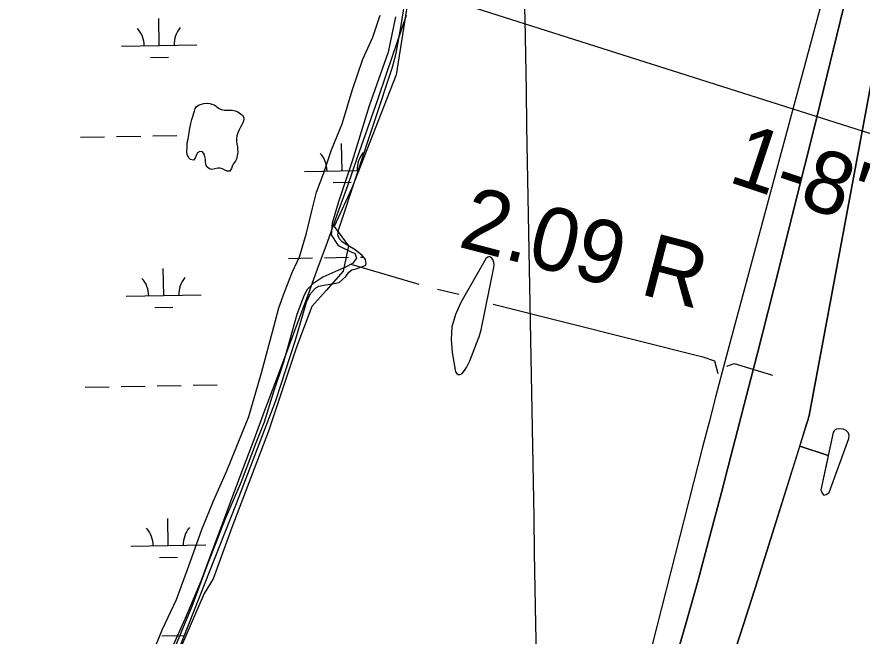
# Model space of a CAD drawing. Extents: x 3925854 to 3964121, y 224593 to 250589.
# Drawn here: x 3940034 to 3941160, y 231956 to 232780 of the extents above; entities that cross this region are included whole.
import ezdxf

# ---------------------------------------------------------------- set-up
doc = ezdxf.new("R2010")
doc.units = 0
for name, color, linetype in [('V-GRID-MAJR', 7, 'Continuous'), ('V-LEVE-TOET', 7, 'Continuous'), ('V-RIVR-EDGE', 7, 'Continuous'), ('V-RIVR-JETY', 7, 'Continuous'), ('V-RIVR-RANG-IDEN', 7, 'Continuous'), ('V-RRAP-FSHR', 7, 'Continuous'), ('V-TOPO-DPTH', 7, 'Continuous'), ('V-TOPO-MINR', 7, 'Continuous'), ('V-TOPO-SHOR', 7, 'Continuous'), ('V-UTIL-IDEN', 7, 'Continuous'), ('V-UTIL-LINE', 7, 'Continuous'), ('V-WETL-SWMP', 7, 'Continuous')]:
    doc.layers.add(name, color=color, linetype=linetype)

msp = doc.modelspace()

# ---------------------------------------------------------------- linework, layer by layer
at = {"layer": 'V-GRID-MAJR'}
msp.add_spline([(3940756.893, 230221.23), (3940647.643, 236278.076), (3940538.337, 242338.005), (3940429.031, 248397.924), (3940428.975, 248401.018)], degree=3, dxfattribs=at)
at = {"layer": 'V-LEVE-TOET'}
for p, q in [((3940478.73, 232450.733), (3940569.213, 232424.402)), ((3940594.108, 232417.387), (3940622.633, 232411.016))]:
    msp.add_line(p, q, dxfattribs=at)
for points in [[(3940668.18, 232397.55), (3940947.413, 232327.718), (3940963.209, 232322.428), (3940967.618, 232305.519)], [(3940979.628, 232315.329), (3940989.284, 232318.454), (3941040.3, 232303.228)]]:
    msp.add_lwpolyline(points, dxfattribs=at)
at = {"layer": 'V-RIVR-EDGE'}
msp.add_lwpolyline([(3940558.753, 232826.474), (3940539.303, 232702.605), (3940479.927, 232552.119), (3940456.382, 232500.933), (3940475.833, 232475.34), (3940468.667, 232441.558), (3940446.145, 232415.965), (3940426.694, 232394.467), (3940406.22, 232340.21), (3940369.366, 232228.626), (3940320.228, 232100.662), (3940295.659, 232032.073), (3940283.375, 232012.622), (3940247.545, 231929.702)], dxfattribs=at)
at = {"layer": 'V-RIVR-JETY'}
for points in [[(3940410.212, 232460.649), (3940419.618, 232492.182), (3940427.876, 232525.294), (3940433.24, 232546.718), (3940442.959, 232572.386), (3940453.138, 232603.126), (3940467.271, 232637.332), (3940481.169, 232683.267), (3940494.604, 232723.733), (3940507.887, 232752.87), (3940517.654, 232782.052)], [(3940538.339, 232779.826), (3940528.339, 232733.058), (3940503.156, 232661.478), (3940480.686, 232587.91), (3940462.381, 232533.826), (3940453.798, 232505.408), (3940452.808, 232489.788), (3940462, 232475.598), (3940481.028, 232466.355), (3940484.145, 232465.532), (3940486.402, 232458.857), (3940481.226, 232451.892), (3940470.603, 232446.561), (3940461.258, 232442.397)], [(3940313.796, 232175.699), (3940342.732, 232248.044), (3940360.007, 232306.044), (3940376.336, 232367.668), (3940382.742, 232392.86), (3940390.406, 232413.525), (3940400.738, 232439.665), (3940410.212, 232460.649)], [(3940461.258, 232442.397), (3940441.366, 232433.417), (3940428.134, 232424.805), (3940420.04, 232416.851), (3940415.897, 232407.424), (3940406.749, 232384.019), (3940389.226, 232320.568), (3940375.412, 232279.559), (3940363.393, 232240.686), (3940352.766, 232213.937), (3940332.712, 232161.359), (3940310.528, 232109.667), (3940286.627, 232048.27), (3940267.182, 231995.395), (3940236.439, 231921.82)], [(3940207.444, 231915.168), (3940227.829, 231965.025), (3940246.501, 232004.572), (3940263.004, 232049.243), (3940280.373, 232097.856), (3940296.032, 232136.162), (3940313.796, 232175.699)]]:
    msp.add_lwpolyline(points, dxfattribs=at)
at = {"layer": 'V-RRAP-FSHR'}
msp.add_lwpolyline([(3940552.433, 232781.786), (3940539.558, 232743.914), (3940526.682, 232706.43), (3940513.806, 232668.173), (3940500.633, 232630.404), (3940487.385, 232592.661), (3940474.136, 232554.919), (3940460.787, 232517.213), (3940447.49, 232479.646), (3940433.309, 232442.791), (3940419.571, 232404.513), (3940405.645, 232367.16), (3940391.602, 232329.563), (3940377.559, 232292.109), (3940363.516, 232254.655), (3940349.472, 232217.201), (3940335.427, 232179.748), (3940321.384, 232142.294), (3940307.343, 232104.84), (3940293.298, 232067.386), (3940279.255, 232029.932), (3940258.246, 231979.478), (3940241.936, 231942.954)], dxfattribs=at)
at = {"layer": 'V-TOPO-DPTH'}
for points in [[(3941197.73, 232828.069), (3941182.541, 232749.068), (3941089.043, 232249.474), (3941088.463, 232246.844), (3941087.715, 232244.258), (3941086.484, 232240.404), (3941086.08, 232239.118), (3941042.756, 232100.204), (3941020.439, 232029.543), (3940997.785, 231958.991), (3940974.625, 231888.603), (3940951.128, 231818.325), (3940831.453, 231527.83), (3940778.585, 231417.807), (3940749.942, 231356.296), (3940722.307, 231294.349), (3940696.185, 231231.75), (3940671.071, 231168.715), (3940471.587, 230649.777), (3940468.564, 230644.623), (3940464.787, 230640.393), (3940233.897, 230211.72)], [(3941076.606, 232208.74), (3941086.08, 232239.118), (3941086.484, 232240.404), (3941087.715, 232244.258), (3941088.463, 232246.844), (3941089.043, 232249.474), (3941182.541, 232749.068), (3941197.73, 232828.069)], [(3940589.961, 231081.241), (3940627.394, 231165.87), (3940800.448, 231552.151), (3940801.441, 231554.375), (3940803.409, 231558.832), (3940805.314, 231563.313), (3940806.969, 231567.884), (3940807.696, 231570.207), (3940908.212, 231914.462), (3940924.869, 231972.465), (3940941.18, 232030.563), (3940956.975, 232088.804), (3940972.426, 232147.139), (3940984.998, 232195.477), (3940993.875, 232229.723), (3941002.714, 232263.978), (3941011.497, 232298.248), (3941020.241, 232332.528), (3941049.078, 232445.972), (3941072.045, 232537.023), (3941094.788, 232628.129), (3941117.196, 232719.318), (3941139.38, 232810.562)], [(3941108.765, 232143.607), (3941112.007, 232144.356), (3941115.854, 232147.185), (3941142.154, 232218.659), (3941142.342, 232223.098), (3941141.312, 232226.774), (3941138.455, 232229.307), (3941134.38, 232231.078), (3941127.905, 232231.725), (3941125.618, 232231.406), (3941123.697, 232230.585), (3941122.323, 232229.01), (3941121.315, 232226.933), (3941114.613, 232196.067), (3941076.606, 232208.74)], [(3941108.765, 232143.607), (3941112.007, 232144.356), (3941115.854, 232147.185), (3941142.154, 232218.659), (3941142.342, 232223.098), (3941141.312, 232226.774), (3941138.455, 232229.307), (3941134.38, 232231.078), (3941127.905, 232231.725), (3941125.618, 232231.406), (3941123.697, 232230.585), (3941122.323, 232229.01), (3941121.315, 232226.933), (3941104.703, 232150.43), (3941106.431, 232145.978), (3941108.765, 232143.607)], [(3941075.21, 232204.264), (3941076.606, 232208.74), (3941114.613, 232196.067), (3941113.153, 232189.344), (3941104.703, 232150.43), (3941106.431, 232145.978), (3941108.765, 232143.607)], [(3940376.027, 230214.305), (3940233.897, 230211.72), (3940464.787, 230640.393), (3940468.564, 230644.623), (3940471.587, 230649.777), (3940671.071, 231168.715), (3940696.185, 231231.75), (3940722.307, 231294.349), (3940749.942, 231356.296), (3940778.585, 231417.807), (3940831.453, 231527.83), (3940951.128, 231818.325), (3940974.625, 231888.603), (3940997.785, 231958.991), (3941020.439, 232029.543), (3941042.756, 232100.204), (3941075.21, 232204.264)]]:
    msp.add_lwpolyline(points, dxfattribs=at)
at = {"layer": 'V-TOPO-MINR'}
for points in [[(3941127.416, 232879.626), (3940982.328, 232340.733), (3940973.425, 232307.411), (3940964.606, 232274.067), (3940955.914, 232240.69), (3940947.307, 232207.29), (3940849.808, 231825.96), (3940838.71, 231783.378), (3940827.35, 231740.867), (3940815.597, 231698.463), (3940803.581, 231656.131), (3940779.662, 231573.33), (3940779.395, 231572.457), (3940778.793, 231570.733), (3940777.755, 231568.196), (3940777.396, 231567.355), (3940777.032, 231566.517), (3940475.423, 230877.328)], [(3941197.73, 232828.069), (3941182.541, 232749.068), (3941089.043, 232249.474), (3941088.463, 232246.844), (3941087.715, 232244.258), (3941086.484, 232240.404), (3941086.08, 232239.118), (3941042.756, 232100.204), (3941020.439, 232029.543), (3940997.785, 231958.991), (3940974.625, 231888.603), (3940951.128, 231818.325), (3940831.453, 231527.83), (3940778.585, 231417.807), (3940749.942, 231356.296), (3940722.307, 231294.349), (3940696.185, 231231.75), (3940671.071, 231168.715), (3940471.587, 230649.777), (3940468.564, 230644.623), (3940464.787, 230640.393), (3940233.897, 230211.72)], [(3941139.38, 232810.562), (3941117.196, 232719.318), (3941094.788, 232628.129), (3941072.045, 232537.023), (3941049.078, 232445.972), (3941020.241, 232332.528), (3941011.497, 232298.248), (3941002.714, 232263.978), (3940993.875, 232229.723), (3940984.998, 232195.477), (3940972.426, 232147.139), (3940956.975, 232088.804), (3940941.18, 232030.563), (3940924.869, 231972.465), (3940908.212, 231914.462), (3940807.696, 231570.207), (3940806.969, 231567.884), (3940805.314, 231563.313), (3940803.409, 231558.832), (3940801.441, 231554.375), (3940800.448, 231552.151), (3940627.394, 231165.87), (3940589.961, 231081.241)], [(3940669.274, 232452.996), (3940668.241, 232456.039), (3940666.691, 232458.976), (3940664.762, 232460.328), (3940662.869, 232460.862), (3940661.028, 232460.167), (3940659.223, 232458.654), (3940625.196, 232399.879), (3940618.151, 232383.948), (3940613.484, 232367.604), (3940612.385, 232350.643), (3940613.664, 232333.27), (3940618.365, 232307.718), (3940619.975, 232305.251), (3940621.886, 232303.848), (3940624.25, 232304.039), (3940626.915, 232305.294), (3940630.044, 232309.167), (3940632.865, 232313.23), (3940635.226, 232317.577), (3940637.279, 232322.113), (3940648.445, 232350.896), (3940649.573, 232354.036), (3940650.595, 232357.208), (3940651.457, 232360.427), (3940652.212, 232363.677), (3940669.276, 232446.481), (3940669.533, 232449.792), (3940669.274, 232452.996)], [(3941108.765, 232143.607), (3941112.007, 232144.356), (3941115.854, 232147.185), (3941142.154, 232218.659), (3941142.342, 232223.098), (3941141.312, 232226.774), (3941138.455, 232229.307), (3941134.38, 232231.078), (3941127.905, 232231.725), (3941125.618, 232231.406), (3941123.697, 232230.585), (3941122.323, 232229.01), (3941121.315, 232226.933), (3941104.703, 232150.43), (3941106.431, 232145.978), (3941108.765, 232143.607)]]:
    msp.add_lwpolyline(points, dxfattribs=at)
at = {"layer": 'V-TOPO-SHOR'}
msp.add_lwpolyline([(3940326.639, 232590.408), (3940325.083, 232587.664), (3940322.42, 232584.934), (3940320.714, 232581.364), (3940319.979, 232578.057), (3940317.587, 232574.772), (3940314.267, 232574.538), (3940310.829, 232575.829), (3940307.949, 232577.664), (3940304.922, 232578.671), (3940301.607, 232578.714), (3940297.724, 232577.662), (3940293.843, 232576.883), (3940290.674, 232577.756), (3940287.662, 232579.867), (3940285.909, 232583.07), (3940285.134, 232587.228), (3940285.04, 232590.546), (3940284.53, 232593.87), (3940283.33, 232597.202), (3940281.436, 232600.128), (3940277.85, 232600.73), (3940274.786, 232598.973), (3940272.803, 232595.406), (3940271.372, 232591.695), (3940269.402, 232589.094), (3940265.406, 232589.976), (3940262.948, 232592.221), (3940260.79, 232596.257), (3940260.44, 232601.099), (3940260.644, 232606.072), (3940261.003, 232612.287), (3940262.035, 232617.249), (3940262.772, 232620.694), (3940263.528, 232625.521), (3940264.437, 232631.592), (3940265.625, 232637.795), (3940267.079, 232643.167), (3940268.515, 232647.154), (3940269.383, 232650.183), (3940270.545, 232654.314), (3940271.695, 232657.755), (3940273.393, 232660.774), (3940276.738, 232662.801), (3940280.07, 232663.864), (3940282.982, 232664.655), (3940287.271, 232665.013), (3940290.861, 232664.687), (3940293.75, 232663.821), (3940296.777, 232662.813), (3940299.518, 232660.98), (3940302.526, 232658.451), (3940305.954, 232656.471), (3940310.642, 232655.58), (3940314.097, 232655.535), (3940317.415, 232655.629), (3940320.872, 232655.721), (3940324.589, 232654.703), (3940328.304, 232653.411), (3940331.729, 232651.017), (3940334.465, 232648.905), (3940336.498, 232645.977), (3940336.457, 232642.798), (3940335.024, 232638.948), (3940333.742, 232636.062), (3940332.044, 232633.044), (3940329.92, 232629.341), (3940328.214, 232625.769), (3940326.912, 232621.364), (3940326.453, 232617.915), (3940326.404, 232614.323), (3940326.772, 232610.862), (3940327.688, 232606.842), (3940328.059, 232603.659), (3940328.155, 232600.476), (3940327.839, 232597.441), (3940326.639, 232590.408)], dxfattribs=at)
at = {"layer": 'V-UTIL-LINE'}
msp.add_lwpolyline([(3944448.956, 231161.167), (3944066.619, 231705.838), (3939716.974, 233085.703), (3938914.857, 233883.421)], dxfattribs=at)
at = {"layer": 'V-WETL-SWMP'}
for p, q in [((3940545.375, 232765.686), (3940550.79, 232798.785)), ((3940223.584, 232741.627), (3940222.93, 232777.621)), ((3940539.121, 232731.769), (3940545.375, 232765.686)), ((3940173.593, 232740.718), (3940273.576, 232742.536)), ((3940211.867, 232725.98), (3940235.863, 232726.417)), ((3940534.446, 232712.758), (3940539.121, 232731.769)), ((3940462.763, 232497.547), (3940534.446, 232712.758)), ((3940270.544, 232654.315), (3940271.695, 232657.755)), ((3940271.695, 232657.755), (3940273.394, 232660.773)), ((3940273.394, 232660.773), (3940276.738, 232662.802)), ((3940276.738, 232662.802), (3940280.069, 232663.864)), ((3940280.069, 232663.864), (3940282.982, 232664.654)), ((3940282.982, 232664.654), (3940287.271, 232665.012)), ((3940287.271, 232665.012), (3940290.86, 232664.688)), ((3940290.86, 232664.688), (3940293.751, 232663.82)), ((3940293.751, 232663.82), (3940296.778, 232662.813)), ((3940296.778, 232662.813), (3940299.518, 232660.98)), ((3940299.518, 232660.98), (3940302.526, 232658.452)), ((3940302.526, 232658.452), (3940305.955, 232656.471)), ((3940267.079, 232643.166), (3940268.514, 232647.155)), ((3940268.514, 232647.155), (3940269.383, 232650.184)), ((3940269.383, 232650.184), (3940270.544, 232654.315)), ((3940305.955, 232656.471), (3940310.642, 232655.58)), ((3940310.642, 232655.58), (3940314.097, 232655.534)), ((3940314.097, 232655.534), (3940317.415, 232655.628)), ((3940317.415, 232655.628), (3940320.872, 232655.721)), ((3940320.872, 232655.721), (3940324.59, 232654.704)), ((3940324.59, 232654.704), (3940328.304, 232653.411)), ((3940328.304, 232653.411), (3940331.728, 232651.016)), ((3940331.728, 232651.016), (3940334.464, 232648.906)), ((3940334.464, 232648.906), (3940336.499, 232645.977)), ((3940264.437, 232631.591), (3940265.625, 232637.795)), ((3940265.625, 232637.795), (3940267.079, 232643.166)), ((3940333.741, 232636.062), (3940332.043, 232633.044)), ((3940335.023, 232638.948), (3940333.741, 232636.062)), ((3940336.457, 232642.799), (3940335.023, 232638.948)), ((3940336.499, 232645.977), (3940336.457, 232642.799)), ((3940262.773, 232620.694), (3940263.528, 232625.522)), ((3940263.528, 232625.522), (3940264.437, 232631.591)), ((3940328.214, 232625.77), (3940326.912, 232621.364)), ((3940329.92, 232629.34), (3940328.214, 232625.77)), ((3940332.043, 232633.044), (3940329.92, 232629.34)), ((3940118.941, 232619.633), (3940150.936, 232620.215)), ((3940166.933, 232620.506), (3940198.928, 232621.088)), ((3940214.925, 232621.379), (3940246.92, 232621.96)), ((3940261.003, 232612.287), (3940262.036, 232617.249)), ((3940262.036, 232617.249), (3940262.773, 232620.694)), ((3940262.917, 232622.251), (3940263.017, 232622.253)), ((3940326.452, 232617.915), (3940326.404, 232614.322)), ((3940326.404, 232614.322), (3940326.773, 232610.862)), ((3940326.912, 232621.364), (3940326.452, 232617.915)), ((3940260.44, 232601.099), (3940260.644, 232606.072)), ((3940260.644, 232606.072), (3940261.003, 232612.287)), ((3940326.773, 232610.862), (3940327.687, 232606.841)), ((3940327.687, 232606.841), (3940328.059, 232603.658)), ((3940328.059, 232603.658), (3940328.155, 232600.477)), ((3940467.122, 232575.214), (3940466.467, 232611.208)), ((3940260.79, 232596.257), (3940260.44, 232601.099)), ((3940262.948, 232592.22), (3940260.79, 232596.257)), ((3940265.406, 232589.976), (3940262.948, 232592.22)), ((3940271.372, 232591.694), (3940269.402, 232589.094)), ((3940272.803, 232595.406), (3940271.372, 232591.694)), ((3940274.785, 232598.974), (3940272.803, 232595.406)), ((3940277.849, 232600.73), (3940274.785, 232598.974)), ((3940281.435, 232600.129), (3940277.849, 232600.73)), ((3940283.331, 232597.202), (3940281.435, 232600.129)), ((3940284.531, 232593.869), (3940283.331, 232597.202)), ((3940285.04, 232590.545), (3940284.531, 232593.869)), ((3940285.134, 232587.227), (3940285.04, 232590.545)), ((3940326.64, 232590.408), (3940325.083, 232587.664)), ((3940327.839, 232597.441), (3940326.64, 232590.408)), ((3940328.155, 232600.477), (3940327.839, 232597.441)), ((3940269.402, 232589.094), (3940265.406, 232589.976)), ((3940285.908, 232583.07), (3940285.134, 232587.227)), ((3940287.662, 232579.868), (3940285.908, 232583.07)), ((3940290.675, 232577.755), (3940287.662, 232579.868)), ((3940320.715, 232581.365), (3940319.98, 232578.057)), ((3940322.421, 232584.935), (3940320.715, 232581.365)), ((3940325.083, 232587.664), (3940322.421, 232584.935)), ((3940293.842, 232576.883), (3940290.675, 232577.755)), ((3940297.723, 232577.661), (3940293.842, 232576.883)), ((3940301.606, 232578.715), (3940297.723, 232577.661)), ((3940304.923, 232578.671), (3940301.606, 232578.715)), ((3940307.95, 232577.664), (3940304.923, 232578.671)), ((3940310.828, 232575.829), (3940307.95, 232577.664)), ((3940314.267, 232574.539), (3940310.828, 232575.829)), ((3940317.587, 232574.772), (3940314.267, 232574.539)), ((3940319.98, 232578.057), (3940317.587, 232574.772)), ((3940417.13, 232574.305), (3940488.764, 232575.607)), ((3940455.404, 232559.567), (3940479.4, 232560.004)), ((3940461.283, 232489.734), (3940462.763, 232497.547)), ((3940463.15, 232485.073), (3940461.283, 232489.734)), ((3940467.096, 232480.434), (3940463.15, 232485.073)), ((3940474.684, 232475.572), (3940467.096, 232480.434)), ((3940484.359, 232469.95), (3940474.684, 232475.572)), ((3940493.796, 232462.247), (3940484.359, 232469.95)), ((3940395.825, 232458.466), (3940427.819, 232459.048)), ((3940443.817, 232459.339), (3940475.811, 232459.921)), ((3940491.809, 232460.212), (3940495.471, 232460.278)), ((3940496.427, 232459.154), (3940493.796, 232462.247)), ((3940498.527, 232457.096), (3940496.427, 232459.154)), ((3940499.1, 232451.903), (3940498.527, 232457.096)), ((3940229.632, 232409.007), (3940228.978, 232445.001)), ((3940479.949, 232443.39), (3940485.914, 232444.75)), ((3940485.914, 232444.75), (3940495.76, 232447.969)), ((3940495.76, 232447.969), (3940498.603, 232449.558)), ((3940498.603, 232449.558), (3940499.1, 232451.903)), ((3940463.222, 232426.584), (3940472.243, 232434.214)), ((3940472.243, 232434.214), (3940476.084, 232439.972)), ((3940476.084, 232439.972), (3940479.949, 232443.39)), ((3940432.358, 232419.512), (3940435.979, 232421.369)), ((3940435.979, 232421.369), (3940445.575, 232423.545)), ((3940445.575, 232423.545), (3940454.403, 232424.675)), ((3940454.403, 232424.675), (3940463.222, 232426.584)), ((3940179.641, 232408.098), (3940279.624, 232409.916)), ((3940419.814, 232400.408), (3940424.897, 232411.898)), ((3940424.897, 232411.898), (3940432.358, 232419.512)), ((3940404.742, 232348.524), (3940419.814, 232400.408)), ((3940217.915, 232393.36), (3940241.911, 232393.797)), ((3940379.026, 232269.497), (3940404.742, 232348.524)), ((3940124.989, 232287.013), (3940156.984, 232287.595)), ((3940172.981, 232287.886), (3940204.976, 232288.468)), ((3940220.973, 232288.759), (3940252.968, 232289.34)), ((3940268.965, 232289.631), (3940300.96, 232290.213)), ((3940326.658, 232132.399), (3940379.026, 232269.497)), ((3940249.056, 231935.831), (3940326.658, 232132.399)), ((3940235.68, 232076.387), (3940235.026, 232112.381)), ((3940185.689, 232075.478), (3940285.672, 232077.296)), ((3940223.963, 232060.74), (3940247.959, 232061.177)), ((3940227.021, 231956.139), (3940257.29, 231956.689))]:
    msp.add_line(p, q, dxfattribs=at)
for centre, start, end in [((3940168.342, 232741.097), 0.269879, 41.813537), ((3940278.809, 232743.106), 140.269876, 181.813534), ((3940411.879, 232574.684), 0.269879, 41.813537), ((3940522.347, 232576.693), 140.269876, 181.813534), ((3940284.857, 232410.486), 140.269876, 181.813534), ((3940174.39, 232408.477), 0.269879, 41.813537), ((3940180.438, 232075.857), 0.269879, 41.813537), ((3940290.906, 232077.866), 140.269876, 181.813534)]:
    msp.add_arc(centre, 35.246, start, end, dxfattribs=at)

# ---------------------------------------------------------------- texts
at = {"layer": 'V-RIVR-RANG-IDEN'}
msp.add_text('2.09 R', height=84, rotation=345.407197, dxfattribs=at).set_placement((3940620.005, 232474.478))
at = {"layer": 'V-UTIL-IDEN'}
msp.add_text('1-8" GAS PIPELINE', height=82.99983, rotation=341.481312, dxfattribs=at).set_placement((3940979.542, 232561.059))

doc.saveas('drawing.dxf')
